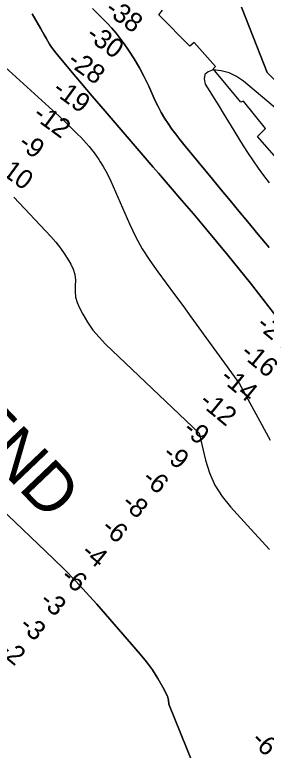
# Model space of a CAD drawing. Extents: x 3245246 to 3283090, y 806824 to 832173.
# Drawn here: x 3268762 to 3269551, y 818378 to 820682 of the extents above; entities that cross this region are included whole.
import ezdxf

# ---------------------------------------------------------------- set-up
doc = ezdxf.new("R2010")
doc.units = 0
for name, color, linetype in [('V-RIVR-IDEN', 7, 'Continuous'), ('V-RIVR-RANG', 7, 'Continuous'), ('V-ROAD-CNTR', 7, 'Continuous'), ('V-RRAP-RVMT', 7, 'Continuous'), ('V-TOPO-DPTH', 7, 'Continuous'), ('V-TOPO-MAJR', 7, 'Continuous'), ('V-TOPO-MINR', 7, 'Continuous')]:
    doc.layers.add(name, color=color, linetype=linetype)

msp = doc.modelspace()

# ---------------------------------------------------------------- linework, layer by layer
at = {"layer": 'V-ROAD-CNTR'}
for points in [[(3268555, 824466.2), (3268928.1, 824288.4), (3269383.1, 824061.9), (3269668.7, 823890.1), (3270076.6, 823640.1), (3270419.3, 823451), (3270842, 823197.9), (3271162.2, 823029.4), (3271548.3, 822792.5), (3271898.4, 822578.4), (3272236.9, 822400.3), (3272509.8, 822239.3), (3272743.9, 822091.3), (3273013.6, 821941.1), (3273341, 821721.2), (3273731.8, 821490.1), (3274189.2, 821175), (3274593.6, 820901.2), (3274916.7, 820684.3), (3275373.2, 820360), (3275676.6, 820161), (3275802.4, 820045.1), (3275896.2, 819928), (3275965.2, 819818.6), (3276015.1, 819699.5), (3276044.4, 819586.7), (3276100.5, 819413), (3276190.9, 819208.3), (3276292.5, 819051.8), (3276415.5, 818926.3), (3276568.2, 818833.9), (3276716.2, 818768.8), (3276924.8, 818729), (3277119.9, 818725), (3277260.8, 818758.2)], [(3265843.1, 823432.9), (3265859, 823417.1), (3265884.4, 823393.5), (3265921.6, 823385.9), (3265988.6, 823351.1), (3266047.2, 823332.3), (3266110.9, 823317.7), (3266174.6, 823302.5), (3266237.9, 823256.1), (3266319, 823213.7), (3266446.2, 823144), (3266598.2, 823070.2), (3266698.3, 823024.2), (3266809.8, 822977.5), (3266902.8, 822954.7), (3266981.5, 822929.4), (3267047, 822922.9), (3267126.7, 822927), (3267196.8, 822934.5), (3267240.8, 822931.2), (3267315.5, 822929), (3267389.5, 822902.9), (3267472.5, 822855.3), (3267548.2, 822799.1), (3267673.2, 822703.2), (3267729.5, 822659.2), (3267800.8, 822580), (3267841.6, 822514.8), (3267890.4, 822443.6), (3267961.5, 822390.3), (3268026.2, 822347.9), (3268097.5, 822313.7), (3268226.8, 822221.5), (3268328.9, 822136.2), (3268438, 822030.2), (3268539.6, 821913.7), (3268611.4, 821855), (3268669.7, 821833), (3268741.6, 821835.2), (3268781, 821862.3), (3268824.2, 821916.6), (3268873.1, 822006.3), (3268932.5, 822098.1), (3268972.1, 822145.5), (3269019.4, 822162), (3269056, 822158.3), (3269086.7, 822138.7), (3269215.7, 821995.6), (3269467.1, 821682.5), (3269665, 821425.3), (3269890.2, 821132.3), (3269935.6, 821060.8), (3269937.8, 820947), (3269911.9, 820878.4), (3269882.4, 820803.4), (3269850.4, 820754.7), (3269820.8, 820702.9), (3269847.5, 820661.4), (3269995.3, 820504.9), (3270135.1, 820342.3), (3270215.8, 820249.2), (3270280.9, 820161.5), (3270409.8, 819983.2), (3270585.2, 819734.7), (3270723.1, 819531.2), (3270847.8, 819342.2), (3270941.2, 819194.9), (3271024.2, 819065), (3271103.7, 818956), (3271217.9, 818809.2), (3271322.1, 818665), (3271450.9, 818481.1), (3271547.8, 818329.9), (3271656.2, 818159), (3271778.9, 817965.4), (3271939, 817707.5), (3272036.6, 817466.5), (3272126.7, 817285.3), (3272211.9, 817051.1), (3272318, 816867.5), (3272429.4, 816683.2), (3272508.6, 816556.2), (3272571.6, 816398.7), (3272670.4, 816197), (3272779.9, 816022.9), (3272872.1, 815803.2), (3272964.7, 815556.6)]]:
    msp.add_spline(points, degree=3, dxfattribs=at)
at = {"layer": 'V-RRAP-RVMT'}
for p, q in [((3269214.1, 820681.3), (3269226, 820696.8)), ((3269214.1, 820681.3), (3269226, 820696.8)), ((3269311.7, 820583.8), (3269214.1, 820681.3)), ((3269311.7, 820583.8), (3269214.1, 820681.3)), ((3269324.9, 820595.2), (3269311.7, 820583.8)), ((3269324.9, 820595.2), (3269311.7, 820583.8)), ((3269391.8, 820520.1), (3269324.9, 820595.2)), ((3269391.8, 820520.1), (3269324.9, 820595.2)), ((3269385.3, 820512.2), (3269391.8, 820520.1)), ((3269385.3, 820512.2), (3269391.8, 820520.1)), ((3269471.8, 820407.8), (3269385.3, 820512.2)), ((3269471.8, 820407.8), (3269385.3, 820512.2)), ((3269479.6, 820411.8), (3269471.8, 820407.8)), ((3269479.6, 820411.8), (3269471.8, 820407.8)), ((3269549, 820325.6), (3269479.6, 820411.8)), ((3269549, 820325.6), (3269479.6, 820411.8)), ((3269524, 820300.8), (3269549, 820325.6)), ((3269524, 820300.8), (3269549, 820325.6)), ((3269692.3, 820106.8), (3269524, 820300.8)), ((3269692.3, 820106.8), (3269524, 820300.8))]:
    msp.add_line(p, q, dxfattribs=at)
at = {"layer": 'V-TOPO-DPTH'}
for points in [[(3270341.5, 819603.5), (3270323.3, 819629.9), (3270304.9, 819656.2), (3270215.7, 819783.2), (3270199.1, 819806.8), (3270182.4, 819830.2), (3270165.6, 819853.6), (3270148.6, 819876.9), (3270131.3, 819899.8), (3270113.6, 819922.5), (3270095.3, 819944.7), (3270076.6, 819966.6), (3269990.1, 820064.9), (3269970.7, 820086.6), (3269951, 820107.9), (3269930.8, 820128.9), (3269910.3, 820149.5), (3269554.1, 820501.5), (3269452.9, 820760.3)], [(3269452.9, 820760.3), (3269554.1, 820501.5), (3269910.3, 820149.5), (3269930.8, 820128.9), (3269951, 820107.9), (3269970.7, 820086.6), (3269990.1, 820064.9), (3270076.6, 819966.6), (3270095.3, 819944.7), (3270113.6, 819922.5), (3270131.3, 819899.8), (3270148.6, 819876.9), (3270165.6, 819853.6), (3270182.4, 819830.2), (3270199.1, 819806.8), (3270215.7, 819783.2), (3270304.9, 819656.2), (3270323.3, 819629.9), (3270341.5, 819603.5)], [(3269006.8, 820701.8), (3269053.4, 820654.8), (3269067.5, 820639.8), (3269081, 820624.3), (3269093.6, 820608.1), (3269105.7, 820591.4), (3269119.2, 820571.5), (3269136.8, 820544.1), (3269153.4, 820516.1), (3269168.6, 820487.3), (3269182.8, 820458), (3269203.3, 820412.6), (3269212.3, 820394.1), (3269221.9, 820375.9), (3269232.5, 820358.2), (3269243.7, 820340.9), (3269255.6, 820324.1), (3269267.8, 820307.4), (3269280.4, 820291.1), (3269293.3, 820275.1), (3269382.4, 820167.2), (3269410.2, 820133.6), (3269438, 820100.1), (3269465.7, 820066.5), (3269493.5, 820033), (3269526.4, 819993.4), (3269537.8, 819979.7), (3269549.3, 819966), (3269560.8, 819952.5)], [(3269560.8, 819952.5), (3269549.3, 819966), (3269537.8, 819979.7), (3269526.4, 819993.4), (3269493.5, 820033), (3269465.7, 820066.5), (3269438, 820100.1), (3269410.2, 820133.6), (3269382.4, 820167.2), (3269293.3, 820275.1), (3269280.4, 820291.1), (3269267.8, 820307.4), (3269255.6, 820324.1), (3269243.7, 820340.9), (3269232.5, 820358.2), (3269221.9, 820375.9), (3269212.3, 820394.1), (3269203.3, 820412.6), (3269182.8, 820458), (3269168.6, 820487.3), (3269153.4, 820516.1), (3269136.8, 820544.1), (3269119.2, 820571.5), (3269105.7, 820591.4), (3269093.6, 820608.1), (3269081, 820624.3), (3269067.5, 820639.8), (3269053.4, 820654.8), (3269006.8, 820701.8)], [(3269598.8, 819716.3), (3269501.4, 819840.9), (3269466.5, 819884.9), (3269431.3, 819928.6), (3269395.6, 819972), (3269359.6, 820015), (3269323.2, 820057.9), (3269286.8, 820100.6), (3269250.2, 820143.2), (3269213.6, 820185.8), (3269197.1, 820204.9), (3269159.4, 820248.5), (3269121.8, 820292.2), (3269084.1, 820335.9), (3269046.5, 820379.6), (3269005.4, 820427.3), (3268988.4, 820447.2), (3268971.4, 820467.1), (3268954.5, 820487.2), (3268937.7, 820507.2), (3268891.3, 820563.1), (3268884.5, 820571.8), (3268877.9, 820580.7), (3268871.9, 820590), (3268866.3, 820599.5), (3268860.8, 820609.1), (3268855.3, 820618.8), (3268849.8, 820628.4), (3268844.2, 820637.9), (3268816.7, 820684.8)], [(3269598.8, 819716.3), (3269501.4, 819840.9), (3269466.5, 819884.9), (3269431.3, 819928.6), (3269395.6, 819972), (3269359.6, 820015), (3269323.2, 820057.9), (3269286.8, 820100.6), (3269250.2, 820143.2), (3269213.6, 820185.8), (3269197.1, 820204.9), (3269159.4, 820248.5), (3269121.8, 820292.2), (3269084.1, 820335.9), (3269046.5, 820379.6), (3269005.4, 820427.3), (3268988.4, 820447.2), (3268971.4, 820467.1), (3268954.5, 820487.2), (3268937.7, 820507.2), (3268891.3, 820563.1), (3268884.5, 820571.8), (3268877.9, 820580.7), (3268871.9, 820590), (3268866.3, 820599.5), (3268860.8, 820609.1), (3268855.3, 820618.8), (3268849.8, 820628.4), (3268844.2, 820637.9), (3268816.7, 820684.8)], [(3268684.9, 820559.4), (3268882.4, 820382.3), (3268891.5, 820374.1), (3268900.5, 820365.8), (3268909.3, 820357.3), (3268918.1, 820348.8), (3268960.6, 820307.3), (3268969.6, 820298.2), (3268978.5, 820289), (3268987, 820279.5), (3268995.4, 820269.8), (3269003.5, 820259.9), (3269011.3, 820249.7), (3269018.7, 820239.4), (3269025.9, 820228.8), (3269030.8, 820221.4), (3269039.8, 820206.8), (3269048.4, 820191.9), (3269056.2, 820176.7), (3269063.5, 820161.1), (3269122.7, 820026.6), (3269141.7, 819987.2), (3269162.4, 819948.9), (3269185.8, 819912.1), (3269210.9, 819876.3), (3269237.2, 819841.3), (3269263.4, 819806.1), (3269289.3, 819770.7), (3269315.2, 819735.3), (3269467, 819525.6), (3269563.2, 819349.2)], [(3268684.9, 820559.4), (3268882.4, 820382.3), (3268891.5, 820374.1), (3268900.5, 820365.8), (3268909.3, 820357.3), (3268918.1, 820348.8), (3268960.6, 820307.3), (3268969.6, 820298.2), (3268978.5, 820289), (3268987, 820279.5), (3268995.4, 820269.8), (3269003.5, 820259.9), (3269011.3, 820249.7), (3269018.7, 820239.4), (3269025.9, 820228.8), (3269030.8, 820221.4), (3269039.8, 820206.8), (3269048.4, 820191.9), (3269056.2, 820176.7), (3269063.5, 820161.1), (3269122.7, 820026.6), (3269141.7, 819987.2), (3269162.4, 819948.9), (3269185.8, 819912.1), (3269210.9, 819876.3), (3269237.2, 819841.3), (3269263.4, 819806.1), (3269289.3, 819770.7), (3269315.2, 819735.3), (3269467, 819525.6), (3269563.2, 819349.2)], [(3269358.9, 818243.2), (3269245.7, 818521.9), (3269245.2, 818534.6), (3269241.4, 818547.8), (3269226.5, 818576), (3269210.9, 818603.2), (3269194.1, 818629.6), (3269175.6, 818654.8), (3269155.8, 818679.1), (3269020.1, 818835.2), (3268987, 818872.2), (3268953.2, 818908.6), (3268918.4, 818944), (3268882.9, 818978.8), (3268291, 819542.6), (3267294.4, 819785)], [(3267294.4, 819785), (3268291, 819542.6), (3268882.9, 818978.8), (3268918.4, 818944), (3268953.2, 818908.6), (3268987, 818872.2), (3269020.1, 818835.2), (3269155.8, 818679.1), (3269175.6, 818654.8), (3269194.1, 818629.6), (3269210.9, 818603.2), (3269226.5, 818576), (3269241.4, 818547.8), (3269245.2, 818534.6), (3269245.7, 818521.9), (3269358.9, 818243.2)]]:
    msp.add_lwpolyline(points, dxfattribs=at)
at = {"layer": 'V-TOPO-MAJR'}
msp.add_lwpolyline([(3269910.4, 820111.7), (3269479.5, 820474.3), (3269457.9, 820488.9), (3269435.1, 820500.1), (3269410.4, 820506.4), (3269384.5, 820509.4), (3269384.3, 820509.4), (3269368.8, 820503.4), (3269358.6, 820494.4), (3269356.4, 820481), (3269359.5, 820464.7), (3269373.9, 820442), (3269388.2, 820419.3), (3269402.3, 820396.5), (3269416.3, 820373.6), (3269449.3, 820319.3), (3269464.1, 820295.3), (3269479.2, 820271.4), (3269494.5, 820247.6), (3269510.1, 820224.1), (3269526.3, 820200.9), (3269542.9, 820178.1), (3269560.3, 820155.8)], dxfattribs=at)
at = {"layer": 'V-TOPO-MINR'}
for points in [[(3270341.5, 819603.5), (3270323.3, 819629.9), (3270304.9, 819656.2), (3270215.7, 819783.2), (3270199.1, 819806.8), (3270182.4, 819830.2), (3270165.6, 819853.6), (3270148.6, 819876.9), (3270131.3, 819899.8), (3270113.6, 819922.5), (3270095.3, 819944.7), (3270076.6, 819966.6), (3269990.1, 820064.9), (3269970.7, 820086.6), (3269951, 820107.9), (3269930.8, 820128.9), (3269910.3, 820149.5), (3269554.1, 820501.5), (3269452.9, 820760.3)], [(3269006.8, 820701.8), (3269053.4, 820654.8), (3269067.5, 820639.8), (3269081, 820624.3), (3269093.6, 820608.1), (3269105.7, 820591.4), (3269119.2, 820571.5), (3269136.8, 820544.1), (3269153.4, 820516.1), (3269168.6, 820487.3), (3269182.8, 820458), (3269203.3, 820412.6), (3269212.3, 820394.1), (3269221.9, 820375.9), (3269232.5, 820358.2), (3269243.7, 820340.9), (3269255.6, 820324.1), (3269267.8, 820307.4), (3269280.4, 820291.1), (3269293.3, 820275.1), (3269382.4, 820167.2), (3269410.2, 820133.6), (3269438, 820100.1), (3269465.7, 820066.5), (3269493.5, 820033), (3269526.4, 819993.4), (3269537.8, 819979.7), (3269549.3, 819966), (3269560.8, 819952.5)], [(3268816.7, 820684.8), (3268844.2, 820637.9), (3268849.8, 820628.4), (3268855.3, 820618.8), (3268860.8, 820609.1), (3268866.3, 820599.5), (3268871.9, 820590), (3268877.9, 820580.7), (3268884.5, 820571.8), (3268891.3, 820563.1), (3268937.7, 820507.2), (3268954.5, 820487.2), (3268971.4, 820467.1), (3268988.4, 820447.2), (3269005.4, 820427.3), (3269046.5, 820379.6), (3269084.1, 820335.9), (3269121.8, 820292.2), (3269159.4, 820248.5), (3269197.1, 820204.9), (3269213.6, 820185.8), (3269250.2, 820143.2), (3269286.8, 820100.6), (3269323.2, 820057.9), (3269359.6, 820015), (3269395.6, 819972), (3269431.3, 819928.6), (3269466.5, 819884.9), (3269501.4, 819840.9), (3269598.8, 819716.3)], [(3268684.9, 820559.4), (3268882.4, 820382.3), (3268891.5, 820374.1), (3268900.5, 820365.8), (3268909.3, 820357.3), (3268918.1, 820348.8), (3268960.6, 820307.3), (3268969.6, 820298.2), (3268978.5, 820289), (3268987, 820279.5), (3268995.4, 820269.8), (3269003.5, 820259.9), (3269011.3, 820249.7), (3269018.7, 820239.4), (3269025.9, 820228.8), (3269030.8, 820221.4), (3269039.8, 820206.8), (3269048.4, 820191.9), (3269056.2, 820176.7), (3269063.5, 820161.1), (3269122.7, 820026.6), (3269141.7, 819987.2), (3269162.4, 819948.9), (3269185.8, 819912.1), (3269210.9, 819876.3), (3269237.2, 819841.3), (3269263.4, 819806.1), (3269289.3, 819770.7), (3269315.2, 819735.3), (3269467, 819525.6), (3269563.2, 819349.2)], [(3268759.2, 820110.9), (3268875.2, 819987.2), (3268891, 819969.2), (3268906, 819950.5), (3268919.7, 819930.9), (3268932.5, 819910.7), (3268938.2, 819901.1), (3268945.8, 819884.8), (3268951, 819868.1), (3268952.8, 819850.6), (3268952.3, 819832.7), (3268951.7, 819814.8), (3268953.3, 819797.2), (3268958.2, 819780.3), (3268965.2, 819763.7), (3268975.9, 819743.9), (3268991.2, 819718.6), (3269007.9, 819694.4), (3269026.9, 819671.9), (3269047.3, 819650.5), (3269340.4, 819370.8), (3269360.6, 819287.2), (3269373.7, 819246.9), (3269390.5, 819208.6), (3269412.8, 819173.3), (3269438.9, 819140), (3269502.5, 819070.4), (3269561.5, 819006.5)], [(3267294.4, 819785), (3268291, 819542.6), (3268882.9, 818978.8), (3268918.4, 818944), (3268953.2, 818908.6), (3268987, 818872.2), (3269020.1, 818835.2), (3269155.8, 818679.1), (3269175.6, 818654.8), (3269194.1, 818629.6), (3269210.9, 818603.2), (3269226.5, 818576), (3269241.4, 818547.8), (3269245.2, 818534.6), (3269245.7, 818521.9), (3269358.9, 818243.2)]]:
    msp.add_lwpolyline(points, dxfattribs=at)

# ---------------------------------------------------------------- texts
at = {"layer": 'V-RIVR-IDEN'}
msp.add_text('BEND', height=150, rotation=313.625, dxfattribs=at).set_placement((3268486.5, 819496))
at = {"layer": 'V-RIVR-RANG'}
for s, rotation, p in [('-38', 323.7592, (3269042, 820690.8)), ('-30', 323.7592, (3268982.5, 820610.4)), ('-28', 323.7592, (3268923.7, 820529.5)), ('-19', 323.7592, (3268877.2, 820439.6)), ('-12', 323.7592, (3268815.8, 820360.7)), ('-9', 323.7592, (3268769.6, 820270.5)), ('-10', 323.7592, (3268698.5, 820198.7)), ('-23', 320.482, (3269516.9, 819704.9)), ('-16', 320.482, (3269466.9, 819616.4)), ('-14', 320.482, (3269403.3, 819539.3)), ('-12', 320.482, (3269337.4, 819464)), ('-9', 320.482, (3269286.2, 819376.6)), ('-9', 320.482, (3269222.4, 819299.6)), ('-6', 320.482, (3269158.4, 819222.8)), ('-8', 320.482, (3269094.2, 819146.1)), ('-6', 320.482, (3269030.7, 819068.8)), ('-4', 320.482, (3268967.1, 818991.7)), ('-6', 320.482, (3268903.1, 818914.9)), ('-3', 320.482, (3268837.1, 818839.7)), ('-3', 320.482, (3268773.3, 818762.7)), ('-2', 320.482, (3268709.8, 818685.4)), ('-6', 314.4298, (3269500.8, 818406.6))]:
    msp.add_text(s, height=60, rotation=rotation, dxfattribs=at).set_placement(p)

doc.saveas('drawing.dxf')
